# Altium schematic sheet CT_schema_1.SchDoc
size 507 x 478 mm
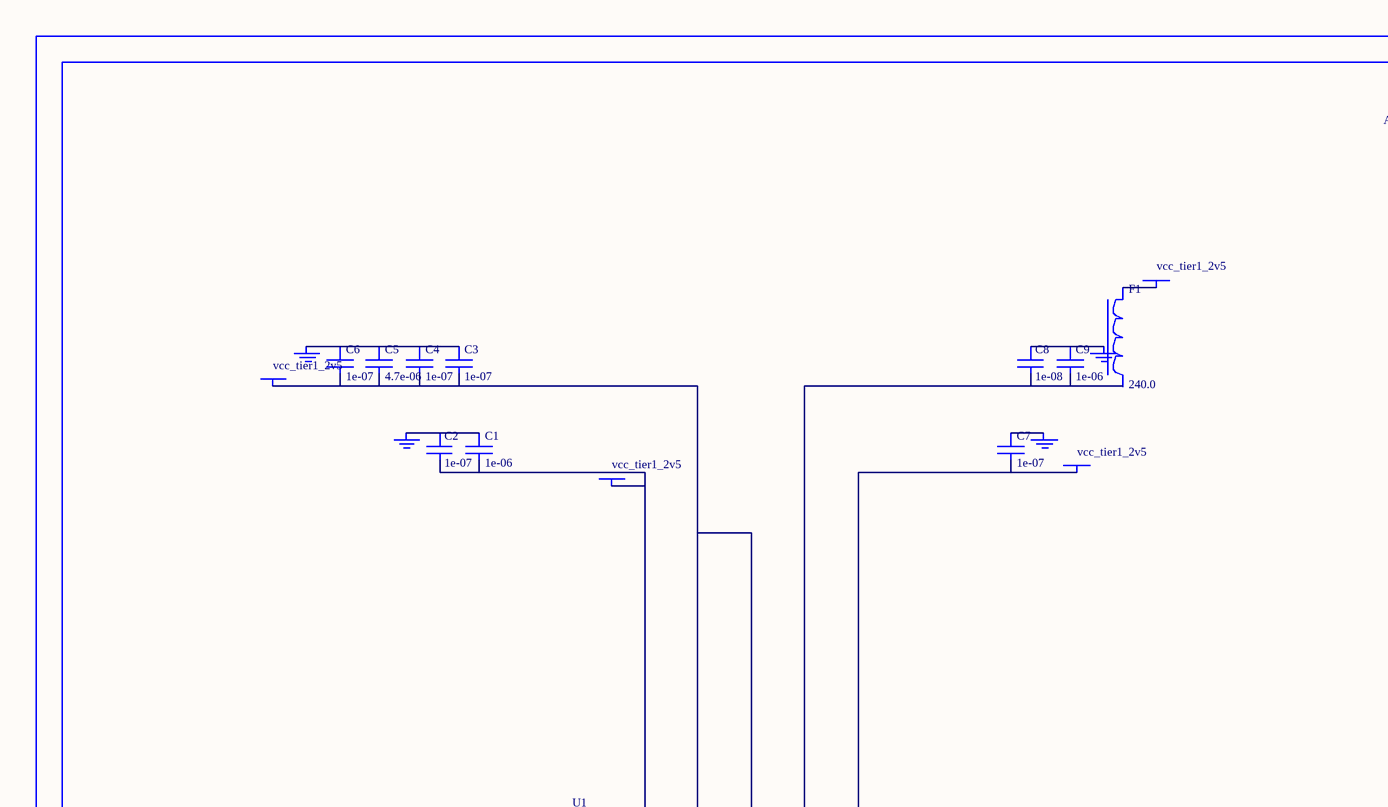
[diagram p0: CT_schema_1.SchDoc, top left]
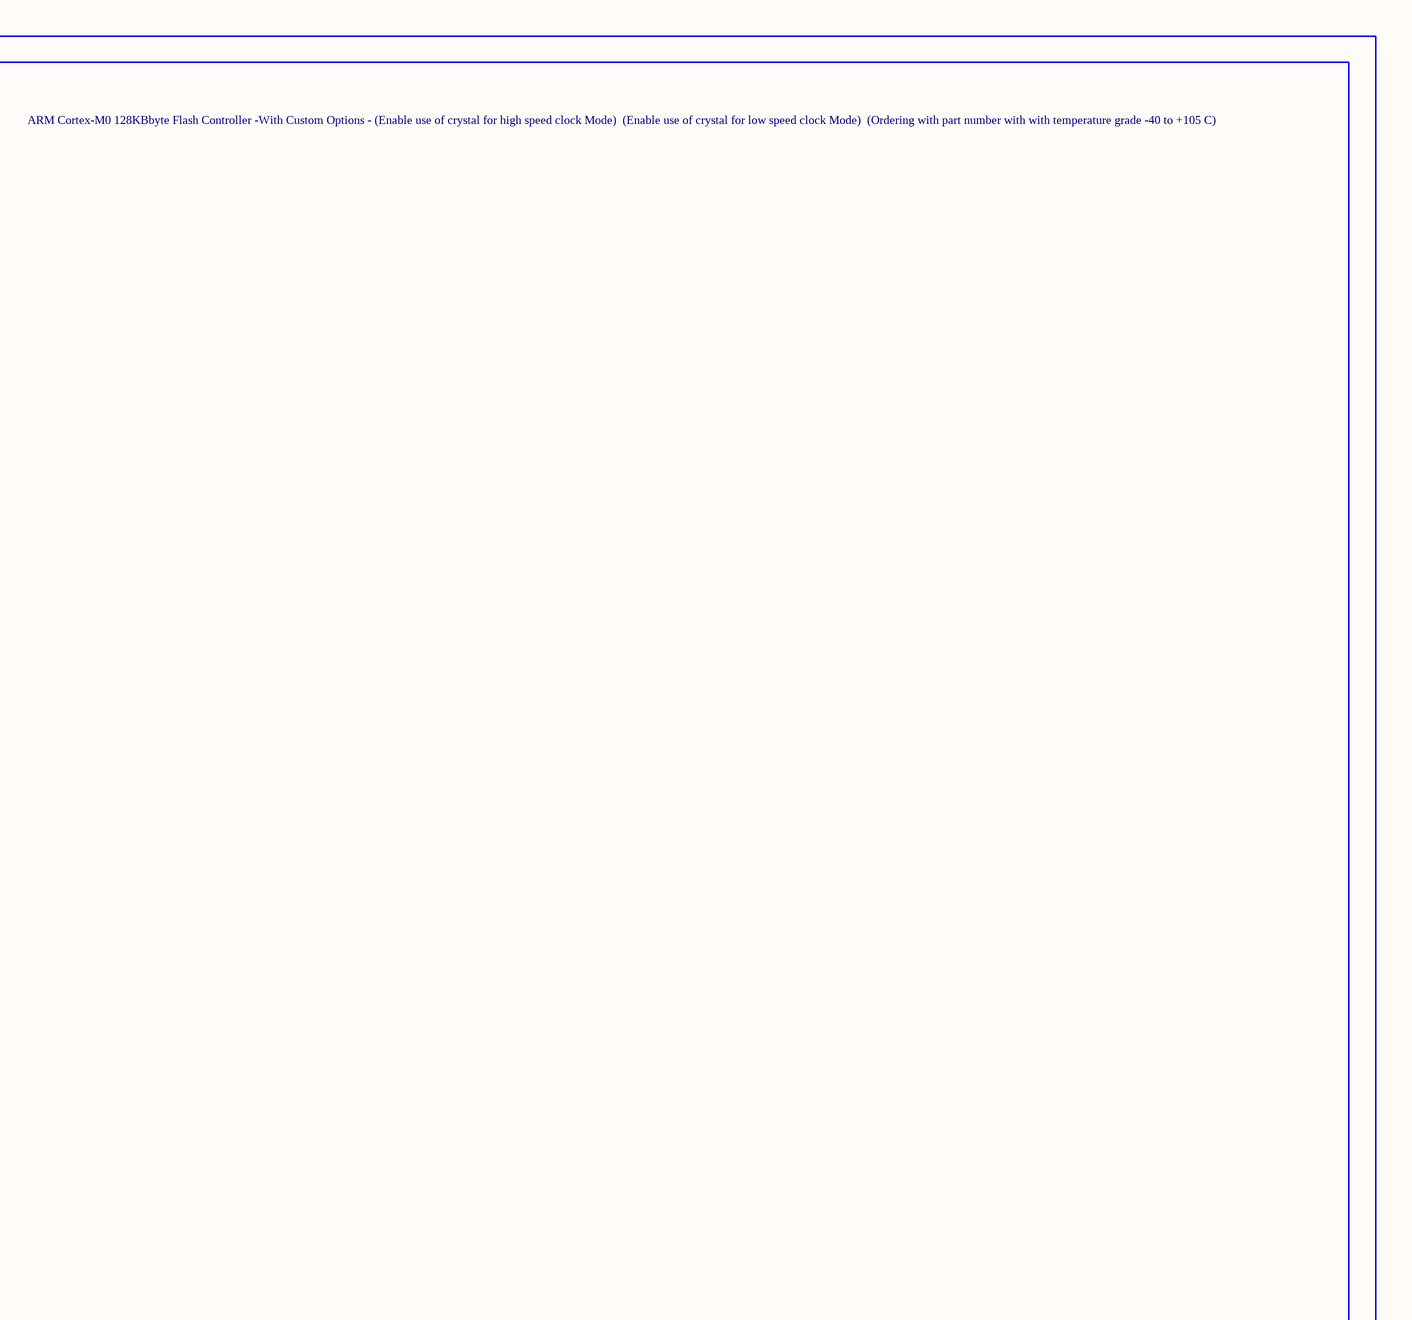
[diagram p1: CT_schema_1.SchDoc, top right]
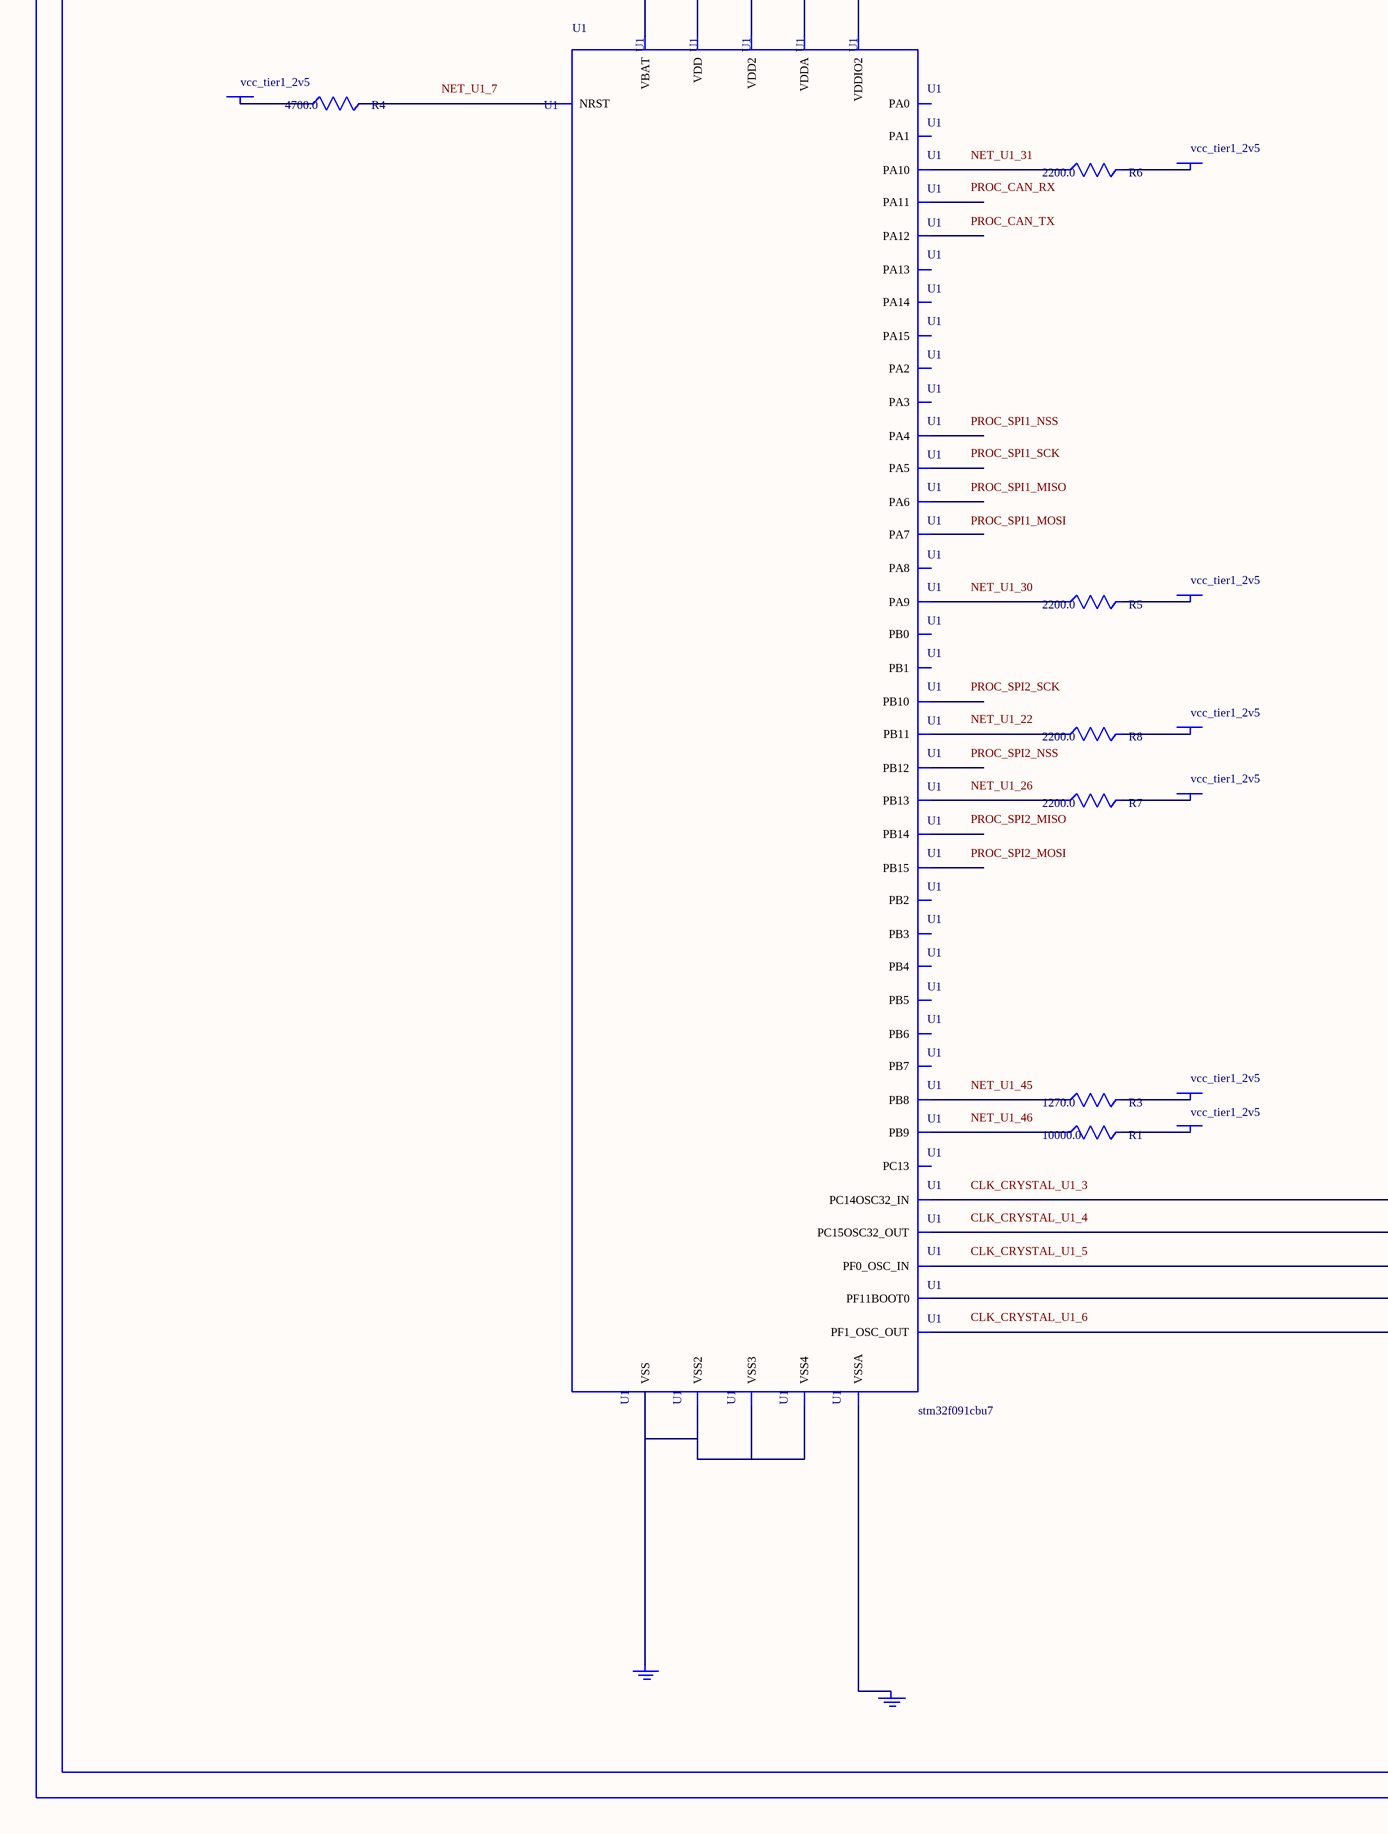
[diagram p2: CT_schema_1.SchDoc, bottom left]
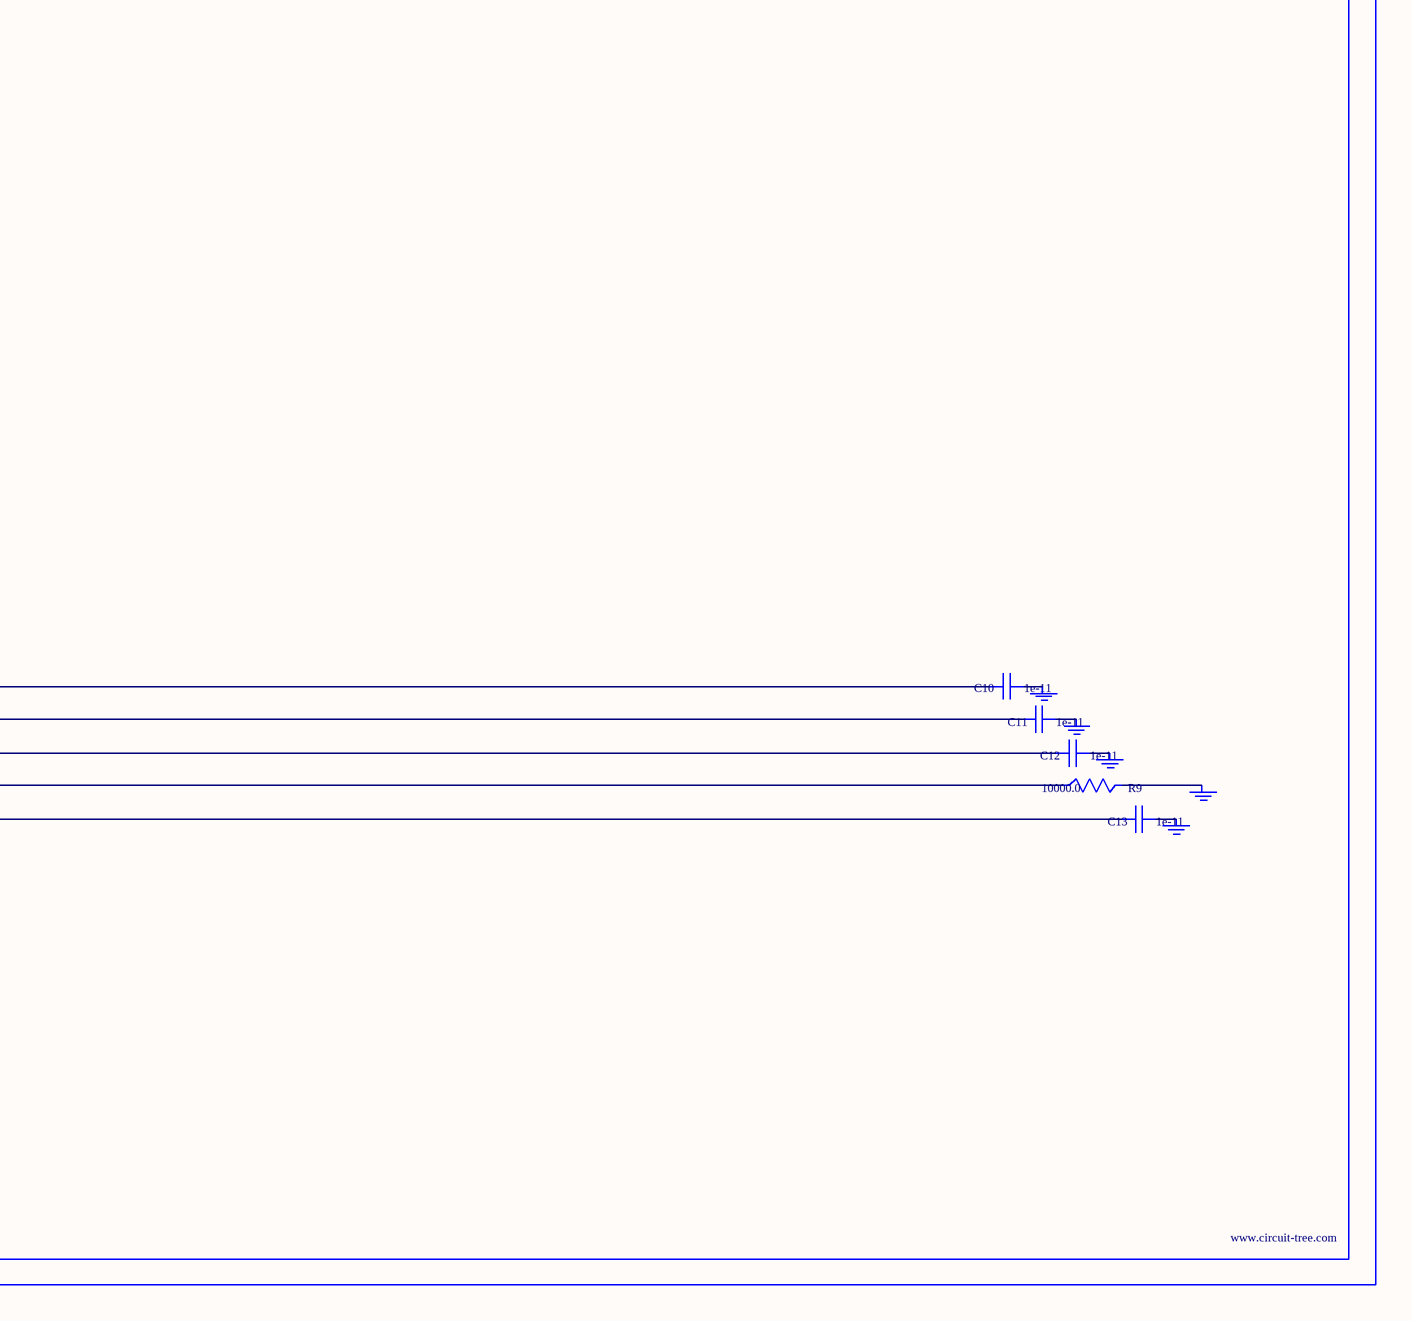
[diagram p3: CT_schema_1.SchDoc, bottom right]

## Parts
BORDER0  (no value)
C1  1e-06  [C0603]
C2  1e-07  [C0603]
C3  1e-07  [C0603]
C4  1e-07  [C0603]
C5  4.7e-06  [C0603]
C6  1e-07  [C0603]
C7  1e-07  [C0603]
C8  1e-08  [C0603]
C9  1e-06  [C0603]
C10  1e-11  [C0402]
C11  1e-11  [C0402]
C12  1e-11  [C0402]
C13  1e-11  [C0402]
F1  240.0  [L0603]
GND_INSTANCE_0_0  (no value)
GND_INSTANCE_0_1  (no value)
GND_INSTANCE_0_2  (no value)
GND_INSTANCE_0_3  (no value)
GND_INSTANCE_0_4  (no value)
GND_INSTANCE_0_5  (no value)
GND_INSTANCE_0_6  (no value)
GND_INSTANCE_0_7  (no value)
GND_INSTANCE_0_8  (no value)
GND_INSTANCE_0_9  (no value)
GND_INSTANCE_0_10  (no value)
POWER_INSTANCE_0_0  vcc_tier1_2v5
POWER_INSTANCE_0_1  vcc_tier1_2v5
POWER_INSTANCE_0_2  vcc_tier1_2v5
POWER_INSTANCE_0_3  vcc_tier1_2v5
POWER_INSTANCE_0_4  vcc_tier1_2v5
POWER_INSTANCE_0_5  vcc_tier1_2v5
POWER_INSTANCE_0_6  vcc_tier1_2v5
POWER_INSTANCE_0_7  vcc_tier1_2v5
POWER_INSTANCE_0_8  vcc_tier1_2v5
POWER_INSTANCE_0_9  vcc_tier1_2v5
POWER_INSTANCE_0_10  vcc_tier1_2v5
R1  10000.0  [R0603]
R3  1270.0  [R0603]
R4  4700.0  [R0603]
R5  2200.0  [R0603]
R6  2200.0  [R0603]
R7  2200.0  [R0603]
R8  2200.0  [R0603]
R9  10000.0  [R0603]
U1  stm32f091cbu7  [UFQFPN48]

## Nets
NetC1_1: C1.1 C2.1 GND_INSTANCE_0_0.0(GND)
NetC1_2: C1.2 C2.2 POWER_INSTANCE_0_0.0(PWR) U1.1(VBAT)
NetC3_1: C3.1 C4.1 C5.1 C6.1 GND_INSTANCE_0_7.0(GND)
NetC3_2: C3.2 C4.2 C5.2 C6.2 POWER_INSTANCE_0_2.0(PWR) U1.24(VDD) U1.48(VDD2)
NetC7_1: C7.1 GND_INSTANCE_0_8.0(GND)
NetC7_2: C7.2 POWER_INSTANCE_0_3.0(PWR) U1.36(VDDIO2)
NetC8_1: C8.1 C9.1 GND_INSTANCE_0_6.0(GND)
NetC8_2: C8.2 C9.2 U1.9(VDDA)
NetC10_1: C10.1 GND_INSTANCE_0_1.0(GND)
NetC10_2: C10.2 U1.3(PC14OSC32_IN)
NetC11_1: C11.1 GND_INSTANCE_0_2.0(GND)
NetC11_2: C11.2 U1.4(PC15OSC32_OUT)
NetC12_1: C12.1 GND_INSTANCE_0_3.0(GND)
NetC12_2: C12.2 U1.5(PF0_OSC_IN)
NetC13_1: C13.1 GND_INSTANCE_0_4.0(GND)
NetC13_2: C13.2 U1.6(PF1_OSC_OUT)
NetF1_1: F1.1 POWER_INSTANCE_0_1.0(PWR)
NetGND_INSTANCE_0_5_0: GND_INSTANCE_0_5.0(GND) U1.8(VSSA)
NetGND_INSTANCE_0_9_0: GND_INSTANCE_0_9.0(GND) R9.2
NetGND_INSTANCE_0_10_0: GND_INSTANCE_0_10.0(GND) U1.23(VSS) U1.35(VSS2) U1.47(VSS3) U1.49(VSS4)
NetPOWER_INSTANCE_0_4_0: POWER_INSTANCE_0_4.0(PWR) R4.1
NetPOWER_INSTANCE_0_5_0: POWER_INSTANCE_0_5.0(PWR) R8.2
NetPOWER_INSTANCE_0_6_0: POWER_INSTANCE_0_6.0(PWR) R7.2
NetPOWER_INSTANCE_0_7_0: POWER_INSTANCE_0_7.0(PWR) R5.2
NetPOWER_INSTANCE_0_8_0: POWER_INSTANCE_0_8.0(PWR) R6.2
NetPOWER_INSTANCE_0_9_0: POWER_INSTANCE_0_9.0(PWR) R3.2
NetPOWER_INSTANCE_0_10_0: POWER_INSTANCE_0_10.0(PWR) R1.2
NetR1_1: R1.1 U1.46(PB9)
NetR3_1: R3.1 U1.45(PB8)
NetR4_2: R4.2 U1.7(NRST)
NetR5_1: R5.1 U1.30(PA9)
NetR6_1: R6.1 U1.31(PA10)
NetR7_1: R7.1 U1.26(PB13)
NetR8_1: R8.1 U1.22(PB11)
NetR9_1: R9.1 U1.44(PF11BOOT0)

Not connected (* = marked no-connect by the designer): F1 2; U1 2(PC13) 10(PA0) 11(PA1) 12(PA2) 13(PA3) 14(PA4) 15(PA5) 16(PA6) 17(PA7) 18(PB0) 19(PB1) 20(PB2) 21(PB10) 25(PB12) 27(PB14) 28(PB15) 29(PA8) 32(PA11) 33(PA12) 34(PA13) 37(PA14) 38(PA15) 39(PB3) 40(PB4) 41(PB5) 42(PB6) 43(PB7)

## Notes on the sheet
- Labels drawn without touching a wire or pin: CLK_CRYSTAL_U1_3, CLK_CRYSTAL_U1_4, CLK_CRYSTAL_U1_5, CLK_CRYSTAL_U1_6, NET_U1_7, NET_U1_22, NET_U1_26, NET_U1_30, NET_U1_31, NET_U1_45, NET_U1_46, PROC_CAN_RX, PROC_CAN_TX, PROC_SPI1_MISO, PROC_SPI1_MOSI, PROC_SPI1_NSS, PROC_SPI1_SCK, PROC_SPI2_MISO, PROC_SPI2_MOSI, PROC_SPI2_NSS, PROC_SPI2_SCK

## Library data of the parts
BORDER0 = BORDER_PAGE0
C1 C9 = C0603C105K3RACTU
C2-C4 C6 C7 = 06035C104K4Z2A
C5 = GRM188R6YA475KE15D
C8 = 06035C103K4Z2A
C10-C13 = C0402C100K3GACTU
F1 = Z0603C241ASMST
GND_INSTANCE_0_0-GND_INSTANCE_0_10 = GND
POWER_INSTANCE_0_0-POWER_INSTANCE_0_10 = PWR
R1 R9 = RC0603JR-0710KL
R3 = RC0603FR-071K27L
R4 = RC0603JR-074K7L
R5-R8 = RC0603JR-072K2L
